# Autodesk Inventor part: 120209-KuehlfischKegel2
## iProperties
Created: 2012-02
Part Number: 120209-KuehlfischKegel2
Document SubType Name: Modeling
Designer: mp
Density: 1 g/cm^3
Author: mp
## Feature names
1. Trennen1
2. Bohrung1 [Hole]
3. Spiegeln1 [Mirror]
4. Rundung1 [Fillet]
5. Runde Anordnung1 [Circular Pattern]
